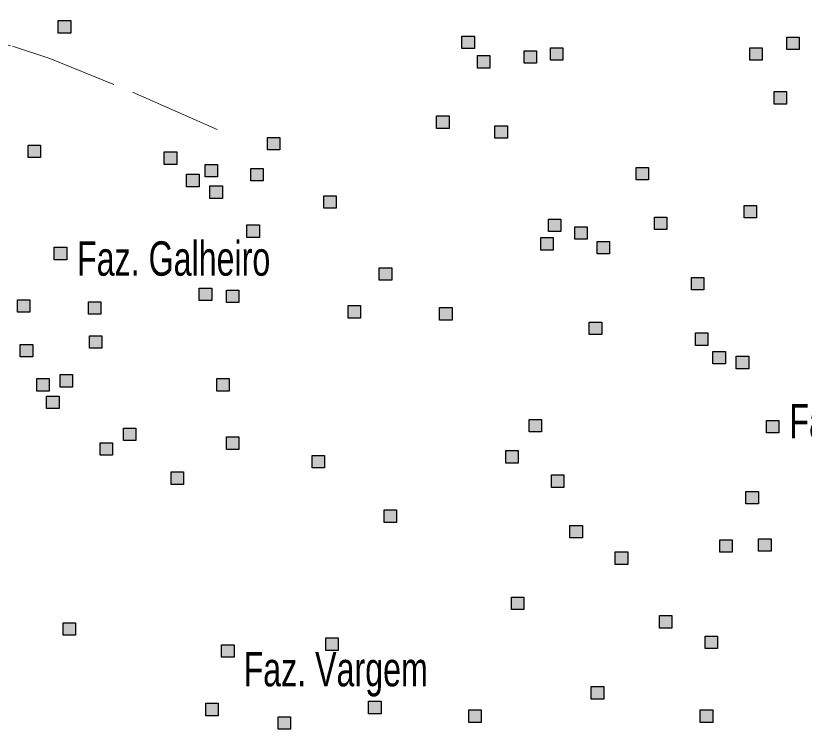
# Model space of a CAD drawing. Extents: x 445.4 to 500, y 8728.7 to 8784.
# Drawn here: x 459.286 to 462.954, y 8733.415 to 8736.735 of the extents above; entities that cross this region are included whole.
import ezdxf
from ezdxf.enums import TextEntityAlignment as Align

# ---------------------------------------------------------------- set-up
doc = ezdxf.new("R2010")
doc.units = 0
doc.header["$LTSCALE"] = 0.064
doc.linetypes.add('DOT_DASHED', pattern=[7.7, 5, -1.2, 0.3, -1.2])
doc.layers.add('2', color=7, linetype='Continuous', lineweight=25)
doc.layers.add('22', color=7, linetype='DOT_DASHED', lineweight=13)
doc.layers.add('61', color=7, linetype='Continuous')

msp = doc.modelspace()

# ---------------------------------------------------------------- hatches: boundary and pattern name
at = {"layer": '2'}
for points in [[(459.4836, 8736.7127), (459.5416, 8736.7127), (459.5416, 8736.6547), (459.4836, 8736.6547)], [(461.3615, 8736.64), (461.4195, 8736.64), (461.4195, 8736.582), (461.3615, 8736.582)], [(462.8728, 8736.6355), (462.9308, 8736.6355), (462.9308, 8736.5775), (462.8728, 8736.5775)], [(461.7732, 8736.5857), (461.8312, 8736.5857), (461.8312, 8736.5277), (461.7732, 8736.5277)], [(462.7009, 8736.5857), (462.7589, 8736.5857), (462.7589, 8736.5277), (462.7009, 8736.5277)], [(461.4339, 8736.5495), (461.4919, 8736.5495), (461.4919, 8736.4915), (461.4339, 8736.4915)], [(461.6511, 8736.5721), (461.7091, 8736.5721), (461.7091, 8736.5141), (461.6511, 8736.5141)], [(462.814, 8736.3819), (462.872, 8736.3819), (462.872, 8736.3239), (462.814, 8736.3239)], [(461.2438, 8736.2688), (461.3018, 8736.2688), (461.3018, 8736.2108), (461.2438, 8736.2108)], [(461.5153, 8736.2235), (461.5733, 8736.2235), (461.5733, 8736.1655), (461.5153, 8736.1655)], [(460.4565, 8736.1692), (460.5145, 8736.1692), (460.5145, 8736.1112), (460.4565, 8736.1112)], [(459.3433, 8736.1332), (459.4013, 8736.1332), (459.4013, 8736.0752), (459.3433, 8736.0752)], [(459.9768, 8736.1015), (460.0348, 8736.1015), (460.0348, 8736.0435), (459.9768, 8736.0435)], [(460.1668, 8736.0427), (460.2248, 8736.0427), (460.2248, 8735.9847), (460.1668, 8735.9847)], [(460.0809, 8735.9974), (460.1389, 8735.9974), (460.1389, 8735.9394), (460.0809, 8735.9394)], [(460.3795, 8736.0243), (460.4375, 8736.0243), (460.4375, 8735.9663), (460.3795, 8735.9663)], [(462.1714, 8736.0288), (462.2294, 8736.0288), (462.2294, 8735.9708), (462.1714, 8735.9708)], [(460.1895, 8735.9431), (460.2475, 8735.9431), (460.2475, 8735.8851), (460.1895, 8735.8851)], [(460.7189, 8735.8975), (460.7769, 8735.8975), (460.7769, 8735.8395), (460.7189, 8735.8395)], [(462.6737, 8735.8522), (462.7317, 8735.8522), (462.7317, 8735.7942), (462.6737, 8735.7942)], [(461.7642, 8735.7888), (461.8222, 8735.7888), (461.8222, 8735.7308), (461.7642, 8735.7308)], [(462.2574, 8735.7979), (462.3154, 8735.7979), (462.3154, 8735.7399), (462.2574, 8735.7399)], [(460.3614, 8735.7617), (460.4194, 8735.7617), (460.4194, 8735.7037), (460.3614, 8735.7037)], [(461.8864, 8735.7526), (461.9444, 8735.7526), (461.9444, 8735.6946), (461.8864, 8735.6946)], [(461.728, 8735.7028), (461.786, 8735.7028), (461.786, 8735.6448), (461.728, 8735.6448)], [(461.9904, 8735.6847), (462.0484, 8735.6847), (462.0484, 8735.6267), (461.9904, 8735.6267)], [(459.4655, 8735.6579), (459.5235, 8735.6579), (459.5235, 8735.5999), (459.4655, 8735.5999)], [(460.9768, 8735.5625), (461.0348, 8735.5625), (461.0348, 8735.5045), (460.9768, 8735.5045)], [(462.4294, 8735.5172), (462.4874, 8735.5172), (462.4874, 8735.4592), (462.4294, 8735.4592)], [(460.1397, 8735.4677), (460.1977, 8735.4677), (460.1977, 8735.4097), (460.1397, 8735.4097)], [(460.2664, 8735.4583), (460.3244, 8735.4583), (460.3244, 8735.4003), (460.2664, 8735.4003)], [(459.2935, 8735.4134), (459.3515, 8735.4134), (459.3515, 8735.3554), (459.2935, 8735.3554)], [(459.6238, 8735.4043), (459.6818, 8735.4043), (459.6818, 8735.3463), (459.6238, 8735.3463)], [(460.832, 8735.3859), (460.89, 8735.3859), (460.89, 8735.3279), (460.832, 8735.3279)], [(461.2574, 8735.3768), (461.3154, 8735.3768), (461.3154, 8735.3188), (461.2574, 8735.3188)], [(461.9542, 8735.3089), (462.0122, 8735.3089), (462.0122, 8735.2509), (461.9542, 8735.2509)], [(459.6284, 8735.2459), (459.6864, 8735.2459), (459.6864, 8735.1879), (459.6284, 8735.1879)], [(462.4475, 8735.2591), (462.5055, 8735.2591), (462.5055, 8735.2011), (462.4475, 8735.2011)], [(459.3071, 8735.2051), (459.3651, 8735.2051), (459.3651, 8735.1471), (459.3071, 8735.1471)], [(462.5289, 8735.1731), (462.5869, 8735.1731), (462.5869, 8735.1151), (462.5289, 8735.1151)], [(462.6375, 8735.1505), (462.6955, 8735.1505), (462.6955, 8735.0925), (462.6375, 8735.0925)], [(459.384, 8735.0466), (459.442, 8735.0466), (459.442, 8734.9886), (459.384, 8734.9886)], [(459.4926, 8735.0648), (459.5506, 8735.0648), (459.5506, 8735.0068), (459.4926, 8735.0068)], [(460.2212, 8735.0463), (460.2792, 8735.0463), (460.2792, 8734.9883), (460.2212, 8734.9883)], [(459.4293, 8734.9652), (459.4873, 8734.9652), (459.4873, 8734.9072), (459.4293, 8734.9072)], [(461.6737, 8734.8562), (461.7317, 8734.8562), (461.7317, 8734.7982), (461.6737, 8734.7982)], [(462.7778, 8734.8517), (462.8358, 8734.8517), (462.8358, 8734.7937), (462.7778, 8734.7937)], [(459.7867, 8734.8157), (459.8447, 8734.8157), (459.8447, 8734.7577), (459.7867, 8734.7577)], [(460.2664, 8734.7747), (460.3244, 8734.7747), (460.3244, 8734.7167), (460.2664, 8734.7167)], [(459.6781, 8734.7478), (459.7361, 8734.7478), (459.7361, 8734.6898), (459.6781, 8734.6898)], [(460.6646, 8734.6887), (460.7226, 8734.6887), (460.7226, 8734.6307), (460.6646, 8734.6307)], [(461.5651, 8734.7113), (461.6231, 8734.7113), (461.6231, 8734.6533), (461.5651, 8734.6533)], [(460.0085, 8734.612), (460.0665, 8734.612), (460.0665, 8734.554), (460.0085, 8734.554)], [(461.7778, 8734.5981), (461.8358, 8734.5981), (461.8358, 8734.5401), (461.7778, 8734.5401)], [(462.6828, 8734.5212), (462.7408, 8734.5212), (462.7408, 8734.4632), (462.6828, 8734.4632)], [(460.9995, 8734.4351), (461.0575, 8734.4351), (461.0575, 8734.3771), (460.9995, 8734.3771)], [(461.8637, 8734.3627), (461.9217, 8734.3627), (461.9217, 8734.3047), (461.8637, 8734.3047)], [(462.5606, 8734.2966), (462.6186, 8734.2966), (462.6186, 8734.2386), (462.5606, 8734.2386)], [(462.7416, 8734.3011), (462.7996, 8734.3011), (462.7996, 8734.2431), (462.7416, 8734.2431)], [(462.075, 8734.2398), (462.133, 8734.2398), (462.133, 8734.1818), (462.075, 8734.1818)], [(461.5922, 8734.0294), (461.6502, 8734.0294), (461.6502, 8733.9714), (461.5922, 8733.9714)], [(462.28, 8733.9434), (462.338, 8733.9434), (462.338, 8733.8854), (462.28, 8733.8854)], [(459.5062, 8733.9103), (459.5642, 8733.9103), (459.5642, 8733.8523), (459.5062, 8733.8523)], [(460.728, 8733.8393), (460.786, 8733.8393), (460.786, 8733.7813), (460.728, 8733.7813)], [(462.4927, 8733.8483), (462.5507, 8733.8483), (462.5507, 8733.7903), (462.4927, 8733.7903)], [(460.2438, 8733.8076), (460.3018, 8733.8076), (460.3018, 8733.7496), (460.2438, 8733.7496)], [(461.9633, 8733.6129), (462.0213, 8733.6129), (462.0213, 8733.5549), (461.9633, 8733.5549)], [(460.9271, 8733.545), (460.9851, 8733.545), (460.9851, 8733.487), (460.9271, 8733.487)], [(460.1697, 8733.5357), (460.2277, 8733.5357), (460.2277, 8733.4777), (460.1697, 8733.4777)], [(461.3931, 8733.5043), (461.4511, 8733.5043), (461.4511, 8733.4463), (461.3931, 8733.4463)], [(462.4701, 8733.5043), (462.5281, 8733.5043), (462.5281, 8733.4463), (462.4701, 8733.4463)], [(460.5062, 8733.4726), (460.5642, 8733.4726), (460.5642, 8733.4146), (460.5062, 8733.4146)]]:
    msp.add_hatch(color=256, dxfattribs=at).paths.add_polyline_path(points)

# ---------------------------------------------------------------- linework, layer by layer
for points in [[(459.4836, 8736.7127), (459.5416, 8736.7127), (459.5416, 8736.6547), (459.4836, 8736.6547)], [(461.3615, 8736.64), (461.4195, 8736.64), (461.4195, 8736.582), (461.3615, 8736.582)], [(462.8728, 8736.6355), (462.9308, 8736.6355), (462.9308, 8736.5775), (462.8728, 8736.5775)], [(461.7732, 8736.5857), (461.8312, 8736.5857), (461.8312, 8736.5277), (461.7732, 8736.5277)], [(462.7009, 8736.5857), (462.7589, 8736.5857), (462.7589, 8736.5277), (462.7009, 8736.5277)], [(461.4339, 8736.5495), (461.4919, 8736.5495), (461.4919, 8736.4915), (461.4339, 8736.4915)], [(461.6511, 8736.5721), (461.7091, 8736.5721), (461.7091, 8736.5141), (461.6511, 8736.5141)], [(462.814, 8736.3819), (462.872, 8736.3819), (462.872, 8736.3239), (462.814, 8736.3239)], [(461.2438, 8736.2688), (461.3018, 8736.2688), (461.3018, 8736.2108), (461.2438, 8736.2108)], [(461.5153, 8736.2235), (461.5733, 8736.2235), (461.5733, 8736.1655), (461.5153, 8736.1655)], [(460.4565, 8736.1692), (460.5145, 8736.1692), (460.5145, 8736.1112), (460.4565, 8736.1112)], [(459.3433, 8736.1332), (459.4013, 8736.1332), (459.4013, 8736.0752), (459.3433, 8736.0752)], [(459.9768, 8736.1015), (460.0348, 8736.1015), (460.0348, 8736.0435), (459.9768, 8736.0435)], [(460.1668, 8736.0427), (460.2248, 8736.0427), (460.2248, 8735.9847), (460.1668, 8735.9847)], [(460.0809, 8735.9974), (460.1389, 8735.9974), (460.1389, 8735.9394), (460.0809, 8735.9394)], [(460.3795, 8736.0243), (460.4375, 8736.0243), (460.4375, 8735.9663), (460.3795, 8735.9663)], [(462.1714, 8736.0288), (462.2294, 8736.0288), (462.2294, 8735.9708), (462.1714, 8735.9708)], [(460.1895, 8735.9431), (460.2475, 8735.9431), (460.2475, 8735.8851), (460.1895, 8735.8851)], [(460.7189, 8735.8975), (460.7769, 8735.8975), (460.7769, 8735.8395), (460.7189, 8735.8395)], [(462.6737, 8735.8522), (462.7317, 8735.8522), (462.7317, 8735.7942), (462.6737, 8735.7942)], [(461.7642, 8735.7888), (461.8222, 8735.7888), (461.8222, 8735.7308), (461.7642, 8735.7308)], [(462.2574, 8735.7979), (462.3154, 8735.7979), (462.3154, 8735.7399), (462.2574, 8735.7399)], [(460.3614, 8735.7617), (460.4194, 8735.7617), (460.4194, 8735.7037), (460.3614, 8735.7037)], [(461.8864, 8735.7526), (461.9444, 8735.7526), (461.9444, 8735.6946), (461.8864, 8735.6946)], [(461.728, 8735.7028), (461.786, 8735.7028), (461.786, 8735.6448), (461.728, 8735.6448)], [(461.9904, 8735.6847), (462.0484, 8735.6847), (462.0484, 8735.6267), (461.9904, 8735.6267)], [(459.4655, 8735.6579), (459.5235, 8735.6579), (459.5235, 8735.5999), (459.4655, 8735.5999)], [(460.9768, 8735.5625), (461.0348, 8735.5625), (461.0348, 8735.5045), (460.9768, 8735.5045)], [(462.4294, 8735.5172), (462.4874, 8735.5172), (462.4874, 8735.4592), (462.4294, 8735.4592)], [(460.1397, 8735.4677), (460.1977, 8735.4677), (460.1977, 8735.4097), (460.1397, 8735.4097)], [(460.2664, 8735.4583), (460.3244, 8735.4583), (460.3244, 8735.4003), (460.2664, 8735.4003)], [(459.2935, 8735.4134), (459.3515, 8735.4134), (459.3515, 8735.3554), (459.2935, 8735.3554)], [(459.6238, 8735.4043), (459.6818, 8735.4043), (459.6818, 8735.3463), (459.6238, 8735.3463)], [(460.832, 8735.3859), (460.89, 8735.3859), (460.89, 8735.3279), (460.832, 8735.3279)], [(461.2574, 8735.3768), (461.3154, 8735.3768), (461.3154, 8735.3188), (461.2574, 8735.3188)], [(461.9542, 8735.3089), (462.0122, 8735.3089), (462.0122, 8735.2509), (461.9542, 8735.2509)], [(459.6284, 8735.2459), (459.6864, 8735.2459), (459.6864, 8735.1879), (459.6284, 8735.1879)], [(462.4475, 8735.2591), (462.5055, 8735.2591), (462.5055, 8735.2011), (462.4475, 8735.2011)], [(459.3071, 8735.2051), (459.3651, 8735.2051), (459.3651, 8735.1471), (459.3071, 8735.1471)], [(462.5289, 8735.1731), (462.5869, 8735.1731), (462.5869, 8735.1151), (462.5289, 8735.1151)], [(462.6375, 8735.1505), (462.6955, 8735.1505), (462.6955, 8735.0925), (462.6375, 8735.0925)], [(459.384, 8735.0466), (459.442, 8735.0466), (459.442, 8734.9886), (459.384, 8734.9886)], [(459.4926, 8735.0648), (459.5506, 8735.0648), (459.5506, 8735.0068), (459.4926, 8735.0068)], [(460.2212, 8735.0463), (460.2792, 8735.0463), (460.2792, 8734.9883), (460.2212, 8734.9883)], [(459.4293, 8734.9652), (459.4873, 8734.9652), (459.4873, 8734.9072), (459.4293, 8734.9072)], [(461.6737, 8734.8562), (461.7317, 8734.8562), (461.7317, 8734.7982), (461.6737, 8734.7982)], [(462.7778, 8734.8517), (462.8358, 8734.8517), (462.8358, 8734.7937), (462.7778, 8734.7937)], [(459.7867, 8734.8157), (459.8447, 8734.8157), (459.8447, 8734.7577), (459.7867, 8734.7577)], [(460.2664, 8734.7747), (460.3244, 8734.7747), (460.3244, 8734.7167), (460.2664, 8734.7167)], [(459.6781, 8734.7478), (459.7361, 8734.7478), (459.7361, 8734.6898), (459.6781, 8734.6898)], [(460.6646, 8734.6887), (460.7226, 8734.6887), (460.7226, 8734.6307), (460.6646, 8734.6307)], [(461.5651, 8734.7113), (461.6231, 8734.7113), (461.6231, 8734.6533), (461.5651, 8734.6533)], [(460.0085, 8734.612), (460.0665, 8734.612), (460.0665, 8734.554), (460.0085, 8734.554)], [(461.7778, 8734.5981), (461.8358, 8734.5981), (461.8358, 8734.5401), (461.7778, 8734.5401)], [(462.6828, 8734.5212), (462.7408, 8734.5212), (462.7408, 8734.4632), (462.6828, 8734.4632)], [(460.9995, 8734.4351), (461.0575, 8734.4351), (461.0575, 8734.3771), (460.9995, 8734.3771)], [(461.8637, 8734.3627), (461.9217, 8734.3627), (461.9217, 8734.3047), (461.8637, 8734.3047)], [(462.5606, 8734.2966), (462.6186, 8734.2966), (462.6186, 8734.2386), (462.5606, 8734.2386)], [(462.7416, 8734.3011), (462.7996, 8734.3011), (462.7996, 8734.2431), (462.7416, 8734.2431)], [(462.075, 8734.2398), (462.133, 8734.2398), (462.133, 8734.1818), (462.075, 8734.1818)], [(461.5922, 8734.0294), (461.6502, 8734.0294), (461.6502, 8733.9714), (461.5922, 8733.9714)], [(462.28, 8733.9434), (462.338, 8733.9434), (462.338, 8733.8854), (462.28, 8733.8854)], [(459.5062, 8733.9103), (459.5642, 8733.9103), (459.5642, 8733.8523), (459.5062, 8733.8523)], [(460.728, 8733.8393), (460.786, 8733.8393), (460.786, 8733.7813), (460.728, 8733.7813)], [(462.4927, 8733.8483), (462.5507, 8733.8483), (462.5507, 8733.7903), (462.4927, 8733.7903)], [(460.2438, 8733.8076), (460.3018, 8733.8076), (460.3018, 8733.7496), (460.2438, 8733.7496)], [(461.9633, 8733.6129), (462.0213, 8733.6129), (462.0213, 8733.5549), (461.9633, 8733.5549)], [(460.9271, 8733.545), (460.9851, 8733.545), (460.9851, 8733.487), (460.9271, 8733.487)], [(460.1697, 8733.5357), (460.2277, 8733.5357), (460.2277, 8733.4777), (460.1697, 8733.4777)], [(461.3931, 8733.5043), (461.4511, 8733.5043), (461.4511, 8733.4463), (461.3931, 8733.4463)], [(462.4701, 8733.5043), (462.5281, 8733.5043), (462.5281, 8733.4463), (462.4701, 8733.4463)], [(460.5062, 8733.4726), (460.5642, 8733.4726), (460.5642, 8733.4146), (460.5062, 8733.4146)]]:
    msp.add_lwpolyline(points, close=True, dxfattribs=at)
at = {"layer": '22'}
msp.add_lwpolyline([(457.9099, 8736.27), (458.0911, 8736.3694), (458.5176, 8736.6037), (458.7273, 8736.7208), (458.7593, 8736.735), (458.9548, 8736.6853), (459.2711, 8736.593), (459.4453, 8736.5362), (459.8292, 8736.38), (460.1171, 8736.2522), (460.2229, 8736.2053)], dxfattribs=at)

# ---------------------------------------------------------------- texts
at = {"layer": '61', "width": 0.7}
for s, p in [('Faz. Galheiro', (459.5711, 8735.5253)), ('Faz. Vargem', (460.3456, 8733.6143))]:
    msp.add_text(s, height=0.16, dxfattribs=at).set_placement(p)
msp.add_text('     Faz. Ipueira', height=0.16, dxfattribs=at).set_placement((463.6755, 8734.7686), align=Align.RIGHT)

doc.saveas('drawing.dxf')
